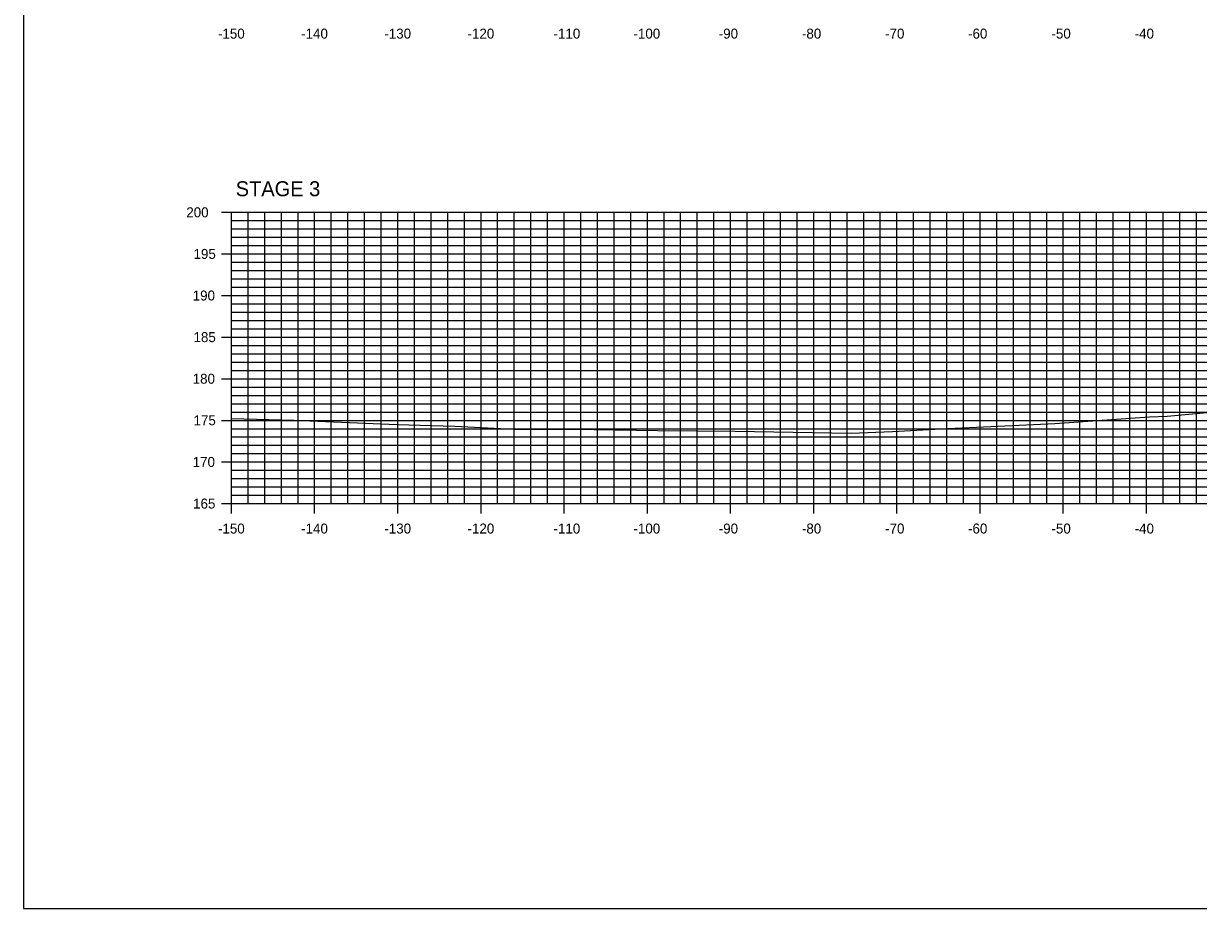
# Model space of a CAD drawing. Extents: x 1405440 to 1409538, y 1842123 to 1843178.
# Drawn here: x 1408707.6 to 1408848.9, y 1842723.5 to 1842829.8 of the extents above; entities that cross this region are included whole.
import ezdxf

# ---------------------------------------------------------------- set-up
doc = ezdxf.new("R2010")
doc.units = 0
for name, color, linetype in [('R_Axis', 7, 'Continuous'), ('R_Axis Annot', 7, 'Continuous'), ('R_Exist Surface', 7, 'Continuous'), ('R_Grid_Minor', 7, 'Continuous'), ('R_Grid_Sta', 7, 'Continuous'), ('R_Grid_Tick', 7, 'Continuous')]:
    doc.layers.add(name, color=color, linetype=linetype)

msp = doc.modelspace()

# ---------------------------------------------------------------- linework, layer by layer
for p, q in [((1408732.62, 1842807.12), (1409032.62, 1842807.12)), ((1408732.62, 1842772.12), (1408732.62, 1842807.12)), ((1408742.62, 1842772.12), (1408742.62, 1842807.12)), ((1408752.62, 1842772.12), (1408752.62, 1842807.12)), ((1408762.62, 1842772.12), (1408762.62, 1842807.12)), ((1408772.62, 1842772.12), (1408772.62, 1842807.12)), ((1408782.62, 1842772.12), (1408782.62, 1842807.12)), ((1408792.62, 1842772.12), (1408792.62, 1842807.12)), ((1408802.62, 1842772.12), (1408802.62, 1842807.12)), ((1408812.62, 1842772.12), (1408812.62, 1842807.12)), ((1408822.62, 1842772.12), (1408822.62, 1842807.12)), ((1408832.62, 1842772.12), (1408832.62, 1842807.12)), ((1408842.62, 1842772.12), (1408842.62, 1842807.12)), ((1408732.62, 1842802.12), (1409032.62, 1842802.12)), ((1408732.62, 1842797.12), (1409032.62, 1842797.12)), ((1408732.62, 1842792.12), (1409032.62, 1842792.12)), ((1408732.62, 1842787.12), (1409032.62, 1842787.12)), ((1408732.62, 1842782.12), (1409032.62, 1842782.12)), ((1408732.62, 1842777.12), (1409032.62, 1842777.12)), ((1408732.62, 1842772.12), (1409032.62, 1842772.12)), ((1408732.62, 1842772.12), (1409032.62, 1842772.12))]:
    msp.add_line(p, q)
msp.add_lwpolyline([(1408707.62, 1842723.47), (1409047.62, 1842723.47), (1409047.62, 1842943.47), (1408707.62, 1842943.47)], close=True)
at = {"layer": 'R_Axis'}
msp.add_line((1408732.62, 1842772.12), (1408732.62, 1842807.12), dxfattribs=at)
at = {"layer": 'R_Exist Surface'}
msp.add_lwpolyline([(1408732.62, 1842782.34), (1408740.12, 1842782.16), (1408752.53, 1842781.64), (1408759.46, 1842781.42), (1408766.51, 1842781.06), (1408776.19, 1842781), (1408783.89, 1842780.9), (1408793.18, 1842780.83), (1408807.12, 1842780.59), (1408812.08, 1842780.77), (1408817.89, 1842781.1), (1408831.59, 1842781.76), (1408842.97, 1842782.55), (1408842.98, 1842782.55), (1408845.09, 1842782.62), (1408851.63, 1842783.23)], dxfattribs=at)
at = {"layer": 'R_Grid_Minor'}
for p, q in [((1408732.62, 1842772.12), (1408732.62, 1842807.12)), ((1408734.62, 1842772.12), (1408734.62, 1842807.12)), ((1408736.62, 1842772.12), (1408736.62, 1842807.12)), ((1408738.62, 1842772.12), (1408738.62, 1842807.12)), ((1408740.62, 1842772.12), (1408740.62, 1842807.12)), ((1408744.62, 1842772.12), (1408744.62, 1842807.12)), ((1408746.62, 1842772.12), (1408746.62, 1842807.12)), ((1408748.62, 1842772.12), (1408748.62, 1842807.12)), ((1408750.62, 1842772.12), (1408750.62, 1842807.12)), ((1408754.62, 1842772.12), (1408754.62, 1842807.12)), ((1408756.62, 1842772.12), (1408756.62, 1842807.12)), ((1408758.62, 1842772.12), (1408758.62, 1842807.12)), ((1408760.62, 1842772.12), (1408760.62, 1842807.12)), ((1408764.62, 1842772.12), (1408764.62, 1842807.12)), ((1408766.62, 1842772.12), (1408766.62, 1842807.12)), ((1408768.62, 1842772.12), (1408768.62, 1842807.12)), ((1408770.62, 1842772.12), (1408770.62, 1842807.12)), ((1408774.62, 1842772.12), (1408774.62, 1842807.12)), ((1408776.62, 1842772.12), (1408776.62, 1842807.12)), ((1408778.62, 1842772.12), (1408778.62, 1842807.12)), ((1408780.62, 1842772.12), (1408780.62, 1842807.12)), ((1408784.62, 1842772.12), (1408784.62, 1842807.12)), ((1408786.62, 1842772.12), (1408786.62, 1842807.12)), ((1408788.62, 1842772.12), (1408788.62, 1842807.12)), ((1408790.62, 1842772.12), (1408790.62, 1842807.12)), ((1408794.62, 1842772.12), (1408794.62, 1842807.12)), ((1408796.62, 1842772.12), (1408796.62, 1842807.12)), ((1408798.62, 1842772.12), (1408798.62, 1842807.12)), ((1408800.62, 1842772.12), (1408800.62, 1842807.12)), ((1408804.62, 1842772.12), (1408804.62, 1842807.12)), ((1408806.62, 1842772.12), (1408806.62, 1842807.12)), ((1408808.62, 1842772.12), (1408808.62, 1842807.12)), ((1408810.62, 1842772.12), (1408810.62, 1842807.12)), ((1408814.62, 1842772.12), (1408814.62, 1842807.12)), ((1408816.62, 1842772.12), (1408816.62, 1842807.12)), ((1408818.62, 1842772.12), (1408818.62, 1842807.12)), ((1408820.62, 1842772.12), (1408820.62, 1842807.12)), ((1408824.62, 1842772.12), (1408824.62, 1842807.12)), ((1408826.62, 1842772.12), (1408826.62, 1842807.12)), ((1408828.62, 1842772.12), (1408828.62, 1842807.12)), ((1408830.62, 1842772.12), (1408830.62, 1842807.12)), ((1408834.62, 1842772.12), (1408834.62, 1842807.12)), ((1408836.62, 1842772.12), (1408836.62, 1842807.12)), ((1408838.62, 1842772.12), (1408838.62, 1842807.12)), ((1408840.62, 1842772.12), (1408840.62, 1842807.12)), ((1408844.62, 1842772.12), (1408844.62, 1842807.12)), ((1408846.62, 1842772.12), (1408846.62, 1842807.12)), ((1408848.62, 1842772.12), (1408848.62, 1842807.12)), ((1408732.62, 1842806.12), (1409032.62, 1842806.12)), ((1408732.62, 1842805.12), (1409032.62, 1842805.12)), ((1408732.62, 1842804.12), (1409032.62, 1842804.12)), ((1408732.62, 1842803.12), (1409032.62, 1842803.12)), ((1408732.62, 1842801.12), (1409032.62, 1842801.12)), ((1408732.62, 1842800.12), (1409032.62, 1842800.12)), ((1408732.62, 1842799.12), (1409032.62, 1842799.12)), ((1408732.62, 1842798.12), (1409032.62, 1842798.12)), ((1408732.62, 1842796.12), (1409032.62, 1842796.12)), ((1408732.62, 1842795.12), (1409032.62, 1842795.12)), ((1408732.62, 1842794.12), (1409032.62, 1842794.12)), ((1408732.62, 1842793.12), (1409032.62, 1842793.12)), ((1408732.62, 1842791.12), (1409032.62, 1842791.12)), ((1408732.62, 1842790.12), (1409032.62, 1842790.12)), ((1408732.62, 1842789.12), (1409032.62, 1842789.12)), ((1408732.62, 1842788.12), (1409032.62, 1842788.12)), ((1408732.62, 1842786.12), (1409032.62, 1842786.12)), ((1408732.62, 1842785.12), (1409032.62, 1842785.12)), ((1408732.62, 1842784.12), (1409032.62, 1842784.12)), ((1408732.62, 1842783.12), (1409032.62, 1842783.12)), ((1408732.62, 1842781.12), (1409032.62, 1842781.12)), ((1408732.62, 1842780.12), (1409032.62, 1842780.12)), ((1408732.62, 1842779.12), (1409032.62, 1842779.12)), ((1408732.62, 1842778.12), (1409032.62, 1842778.12)), ((1408732.62, 1842776.12), (1409032.62, 1842776.12)), ((1408732.62, 1842775.12), (1409032.62, 1842775.12)), ((1408732.62, 1842774.12), (1409032.62, 1842774.12)), ((1408732.62, 1842773.12), (1409032.62, 1842773.12))]:
    msp.add_line(p, q, dxfattribs=at)
at = {"layer": 'R_Grid_Tick'}
for p, q in [((1408731.42, 1842807.12), (1408733.82, 1842807.12)), ((1408732.62, 1842806.12), (1408733.22, 1842806.12)), ((1408732.62, 1842805.12), (1408733.22, 1842805.12)), ((1408732.62, 1842804.12), (1408733.22, 1842804.12)), ((1408732.62, 1842803.12), (1408733.22, 1842803.12)), ((1408731.42, 1842802.12), (1408733.82, 1842802.12)), ((1408732.62, 1842801.12), (1408733.22, 1842801.12)), ((1408732.62, 1842800.12), (1408733.22, 1842800.12)), ((1408732.62, 1842799.12), (1408733.22, 1842799.12)), ((1408731.42, 1842797.12), (1408733.82, 1842797.12)), ((1408732.62, 1842798.12), (1408733.22, 1842798.12)), ((1408732.62, 1842796.12), (1408733.22, 1842796.12)), ((1408732.62, 1842795.12), (1408733.22, 1842795.12)), ((1408732.62, 1842794.12), (1408733.22, 1842794.12)), ((1408732.62, 1842793.12), (1408733.22, 1842793.12)), ((1408731.42, 1842792.12), (1408733.82, 1842792.12)), ((1408732.62, 1842791.12), (1408733.22, 1842791.12)), ((1408732.62, 1842790.12), (1408733.22, 1842790.12)), ((1408732.62, 1842789.12), (1408733.22, 1842789.12)), ((1408732.62, 1842788.12), (1408733.22, 1842788.12)), ((1408731.42, 1842787.12), (1408733.82, 1842787.12)), ((1408732.62, 1842786.12), (1408733.22, 1842786.12)), ((1408732.62, 1842785.12), (1408733.22, 1842785.12)), ((1408732.62, 1842784.12), (1408733.22, 1842784.12)), ((1408732.62, 1842783.12), (1408733.22, 1842783.12)), ((1408731.42, 1842782.12), (1408733.82, 1842782.12)), ((1408732.62, 1842781.12), (1408733.22, 1842781.12)), ((1408732.62, 1842780.12), (1408733.22, 1842780.12)), ((1408732.62, 1842779.12), (1408733.22, 1842779.12)), ((1408732.62, 1842778.12), (1408733.22, 1842778.12)), ((1408731.42, 1842777.12), (1408733.82, 1842777.12)), ((1408732.62, 1842776.12), (1408733.22, 1842776.12)), ((1408732.62, 1842775.12), (1408733.22, 1842775.12)), ((1408732.62, 1842774.12), (1408733.22, 1842774.12)), ((1408732.62, 1842770.92), (1408732.62, 1842773.32)), ((1408732.62, 1842773.12), (1408733.22, 1842773.12)), ((1408742.62, 1842770.92), (1408742.62, 1842773.32)), ((1408752.62, 1842770.92), (1408752.62, 1842773.32)), ((1408762.62, 1842770.92), (1408762.62, 1842773.32)), ((1408772.62, 1842770.92), (1408772.62, 1842773.32)), ((1408782.62, 1842770.92), (1408782.62, 1842773.32)), ((1408792.62, 1842770.92), (1408792.62, 1842773.32)), ((1408802.62, 1842770.92), (1408802.62, 1842773.32)), ((1408812.62, 1842770.92), (1408812.62, 1842773.32)), ((1408822.62, 1842770.92), (1408822.62, 1842773.32)), ((1408832.62, 1842770.92), (1408832.62, 1842773.32)), ((1408842.62, 1842770.92), (1408842.62, 1842773.32)), ((1408731.42, 1842772.12), (1408733.82, 1842772.12)), ((1408732.62, 1842772.12), (1408732.62, 1842772.72)), ((1408734.62, 1842772.12), (1408734.62, 1842772.72)), ((1408736.62, 1842772.12), (1408736.62, 1842772.72)), ((1408738.62, 1842772.12), (1408738.62, 1842772.72)), ((1408740.62, 1842772.12), (1408740.62, 1842772.72)), ((1408744.62, 1842772.12), (1408744.62, 1842772.72)), ((1408746.62, 1842772.12), (1408746.62, 1842772.72)), ((1408748.62, 1842772.12), (1408748.62, 1842772.72)), ((1408750.62, 1842772.12), (1408750.62, 1842772.72)), ((1408754.62, 1842772.12), (1408754.62, 1842772.72)), ((1408756.62, 1842772.12), (1408756.62, 1842772.72)), ((1408758.62, 1842772.12), (1408758.62, 1842772.72)), ((1408760.62, 1842772.12), (1408760.62, 1842772.72)), ((1408764.62, 1842772.12), (1408764.62, 1842772.72)), ((1408766.62, 1842772.12), (1408766.62, 1842772.72)), ((1408768.62, 1842772.12), (1408768.62, 1842772.72)), ((1408770.62, 1842772.12), (1408770.62, 1842772.72)), ((1408774.62, 1842772.12), (1408774.62, 1842772.72)), ((1408776.62, 1842772.12), (1408776.62, 1842772.72)), ((1408778.62, 1842772.12), (1408778.62, 1842772.72)), ((1408780.62, 1842772.12), (1408780.62, 1842772.72)), ((1408784.62, 1842772.12), (1408784.62, 1842772.72)), ((1408786.62, 1842772.12), (1408786.62, 1842772.72)), ((1408788.62, 1842772.12), (1408788.62, 1842772.72)), ((1408790.62, 1842772.12), (1408790.62, 1842772.72)), ((1408794.62, 1842772.12), (1408794.62, 1842772.72)), ((1408796.62, 1842772.12), (1408796.62, 1842772.72)), ((1408798.62, 1842772.12), (1408798.62, 1842772.72)), ((1408800.62, 1842772.12), (1408800.62, 1842772.72)), ((1408804.62, 1842772.12), (1408804.62, 1842772.72)), ((1408806.62, 1842772.12), (1408806.62, 1842772.72)), ((1408808.62, 1842772.12), (1408808.62, 1842772.72)), ((1408810.62, 1842772.12), (1408810.62, 1842772.72)), ((1408814.62, 1842772.12), (1408814.62, 1842772.72)), ((1408816.62, 1842772.12), (1408816.62, 1842772.72)), ((1408818.62, 1842772.12), (1408818.62, 1842772.72)), ((1408820.62, 1842772.12), (1408820.62, 1842772.72)), ((1408824.62, 1842772.12), (1408824.62, 1842772.72)), ((1408826.62, 1842772.12), (1408826.62, 1842772.72)), ((1408828.62, 1842772.12), (1408828.62, 1842772.72)), ((1408830.62, 1842772.12), (1408830.62, 1842772.72)), ((1408834.62, 1842772.12), (1408834.62, 1842772.72)), ((1408836.62, 1842772.12), (1408836.62, 1842772.72)), ((1408838.62, 1842772.12), (1408838.62, 1842772.72)), ((1408840.62, 1842772.12), (1408840.62, 1842772.72)), ((1408844.62, 1842772.12), (1408844.62, 1842772.72)), ((1408846.62, 1842772.12), (1408846.62, 1842772.72)), ((1408848.62, 1842772.12), (1408848.62, 1842772.72))]:
    msp.add_line(p, q, dxfattribs=at)

# ---------------------------------------------------------------- texts
at = {"layer": 'R_Axis'}
msp.add_text('-', height=0.0001, dxfattribs=at).set_placement((1408732.62, 1842772.12))
at = {"layer": 'R_Axis Annot'}
for s, p in [('-150', (1408731, 1842827.99)), ('-140', (1408741, 1842827.99)), ('-130', (1408751, 1842827.99)), ('-120', (1408761, 1842827.99)), ('-110', (1408771.34, 1842827.99)), ('-100', (1408780.95, 1842827.99)), ('-90', (1408791.2, 1842827.99)), ('-80', (1408801.2, 1842827.99)), ('-70', (1408811.2, 1842827.99)), ('-60', (1408821.17, 1842827.99)), ('-50', (1408831.2, 1842827.99)), ('-40', (1408841.2, 1842827.99)), ('200', (1408727.19, 1842806.52)), ('195', (1408728.06, 1842801.52)), ('190', (1408727.96, 1842796.52)), ('185', (1408728.06, 1842791.52)), ('180', (1408727.96, 1842786.52)), ('175', (1408728.06, 1842781.52)), ('170', (1408727.96, 1842776.52)), ('165', (1408728.01, 1842771.52)), ('-150', (1408731, 1842768.52)), ('-140', (1408741, 1842768.52)), ('-130', (1408751, 1842768.52)), ('-120', (1408761, 1842768.52)), ('-110', (1408771.34, 1842768.52)), ('-100', (1408780.95, 1842768.52)), ('-90', (1408791.2, 1842768.52)), ('-80', (1408801.2, 1842768.52)), ('-70', (1408811.2, 1842768.52)), ('-60', (1408821.17, 1842768.52)), ('-50', (1408831.2, 1842768.52)), ('-40', (1408841.2, 1842768.52))]:
    msp.add_text(s, height=1.2, dxfattribs=at).set_placement(p)
at = {"layer": 'R_Grid_Sta'}
msp.add_text('STAGE 3', height=1.8, dxfattribs=at).set_placement((1408733.13, 1842809.05))

doc.saveas('drawing.dxf')
